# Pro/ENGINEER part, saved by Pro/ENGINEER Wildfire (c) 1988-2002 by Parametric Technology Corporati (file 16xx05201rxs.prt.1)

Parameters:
  HERSTELLER = "Hersteller"
  NB = "16XX05201RXS"
  NN = "16-R"
  NT = "16 Series - Rigid"
  NBSYN = "$PN.$RIGS.$T."
  LINA = "16XX05201RXS"
  PN = "16XX05201"
  RIGS = "R"
  T = "XS"
  DIA = "5"
  WIDTH = "2"
  A = "2.44"
  B = "4.000"
  C = "3.75"
  WW1 = "2.000"
  T1 = "'XS','MR','PB','XA','CA','TM','NG','XI','PI','PD','XP','CH'"
  PN1 = "XS0520112"
  AXLE = "1"
  KT = "DUMMY"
